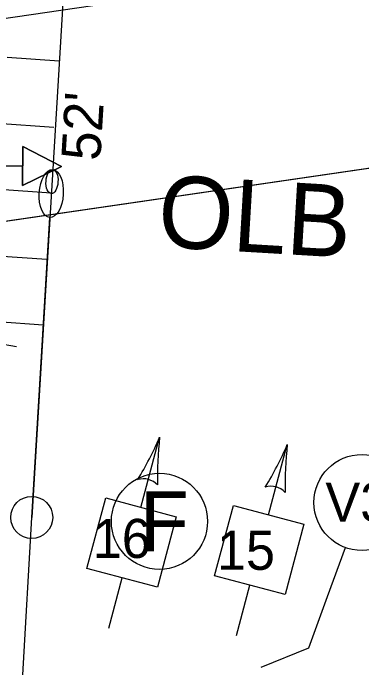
# Model space of a CAD drawing. Extents: x 647787 to 668496, y 640478 to 654412.
# Drawn here: x 661890.8 to 661919.8, y 647241.2 to 647296.2 of the extents above; entities that cross this region are included whole.
import ezdxf

# ---------------------------------------------------------------- set-up
doc = ezdxf.new("R2010")
doc.units = 0
for name, color, linetype in [('Default', 7, 'Continuous'), ('TEMP_SIGNAL_HEAD_STAGE 2', 7, 'Continuous'), ('TEMP_SIGNAL_HEAD_Stage 3', 7, 'Continuous'), ('TEMP_SIGNAL_HEAD_STAGE 4 SHILO', 7, 'Continuous'), ('TEMP_SIGNAL_HEAD_STAGE4', 7, 'Continuous'), ('TEMP_SIGNAL_POLES_STAGE 1A', 7, 'Continuous'), ('TEMP_SIGNAL_POLES_STAGE 5', 7, 'Continuous'), ('TEXT_TEMP_SIGNAL_POLES_STAGE 2', 7, 'Continuous'), ('TEXT_TEMP_SIGNAL_POLES_STAGE 5', 7, 'Continuous')]:
    doc.layers.add(name, color=color, linetype=linetype)

msp = doc.modelspace()

# ---------------------------------------------------------------- linework, layer by layer
at = {"layer": 'Default'}
for points in [[(662136.439, 647331.769), (661882.019, 647294.613), (661114.402, 647320.889)], [(662108.288, 647310.771), (661853.868, 647273.614), (661086.251, 647299.89)], [(662108.288, 647310.771), (661888.554, 647278.68)], [(662108.288, 647310.771), (661888.554, 647278.68)]]:
    msp.add_lwpolyline(points, dxfattribs=at)
at = {"layer": 'TEMP_SIGNAL_HEAD_STAGE 2'}
for p, q in [((661901.432, 647255.118), (661902.988, 647260.955)), ((661912.052, 647254.503), (661913.608, 647260.339)), ((661916.966, 647247.7), (661918.451, 647251.767)), ((661898.749, 647245.06), (661899.869, 647249.26)), ((661909.369, 647244.444), (661910.489, 647248.645)), ((661915.407, 647243.43), (661916.966, 647247.7)), ((661911.445, 647241.82), (661915.407, 647243.43))]:
    msp.add_line(p, q, dxfattribs=at)
for points in [[(661902.799, 647248.479), (661896.94, 647250.041), (661898.502, 647255.9), (661904.362, 647254.337)], [(661913.419, 647247.863), (661907.56, 647249.426), (661909.122, 647255.284), (661914.982, 647253.722)]]:
    msp.add_lwpolyline(points, close=True, dxfattribs=at)
msp.add_circle((661919.824, 647255.525), 4, dxfattribs=at)
for centre, radius, start, end in [((661875.97, 647272.726), 29.472, 328.7206, 336.4587), ((661932.282, 647257.708), 29.472, 173.6753, 181.4134), ((661886.59, 647272.111), 29.472, 328.7206, 336.4587), ((661942.902, 647257.093), 29.472, 173.6753, 181.4134), ((661901.632, 647255.866), 1.629, 43.2197, 106.9143), ((661912.252, 647255.25), 1.629, 43.2197, 106.9143)]:
    msp.add_arc(centre, radius, start, end, dxfattribs=at)
at = {"layer": 'TEMP_SIGNAL_HEAD_Stage 3'}
msp.add_line((661891.067, 647268.477), (661876.801, 647271.004), dxfattribs=at)
at = {"layer": 'TEMP_SIGNAL_HEAD_STAGE 4 SHILO'}
for points in [[(661891.574, 647281.911), (661891.611, 647285.148), (661894.818, 647283.492), (661891.574, 647281.911)], [(661891.574, 647281.911), (661891.611, 647285.148), (661894.818, 647283.492), (661891.574, 647281.911)], [(661889.993, 647283.548), (661891.593, 647283.53)], [(661889.993, 647283.548), (661891.593, 647283.53)]]:
    msp.add_lwpolyline(points, dxfattribs=at)
msp.add_lwpolyline([(661894.818, 647283.492), (661891.611, 647285.148), (661891.574, 647281.911)], close=True, dxfattribs=at)
msp.add_lwpolyline([(661894.818, 647283.492), (661891.611, 647285.148), (661891.574, 647281.911)], close=True, dxfattribs=at)
at = {"layer": 'TEMP_SIGNAL_HEAD_STAGE4'}
msp.add_line((661891.067, 647268.477), (661876.801, 647271.004), dxfattribs=at)
at = {"layer": 'TEMP_SIGNAL_POLES_STAGE 1A'}
for p, q in [((661895.478, 647306.186), (661892.345, 647254.281)), ((661894.637, 647292.251), (661890.3, 647292.547)), ((661883.789, 647287.48), (661894.174, 647286.77)), ((661893.974, 647281.271), (661889.637, 647281.567)), ((661892.345, 647254.281), (661893.851, 647279.236)), ((661883.213, 647276.494), (661893.599, 647275.784)), ((661893.311, 647270.29), (661888.974, 647270.587))]:
    msp.add_line(p, q, dxfattribs=at)
msp.add_circle((661892.345, 647254.281), 1.75, dxfattribs=at)
for centre, major_axis in [((661893.972, 647281.232), (0.121, 1.996)), ((661894.032, 647282.23), (-0.06, -0.998))]:
    msp.add_ellipse(centre, major_axis=major_axis, ratio=0.5, dxfattribs=at)
at = {"layer": 'TEMP_SIGNAL_POLES_STAGE 5'}
for p, q in [((661895.478, 647306.186), (661892.345, 647254.281)), ((661892.345, 647254.281), (661893.851, 647279.236)), ((661891.611, 647241.188), (661892.345, 647254.281))]:
    msp.add_line(p, q, dxfattribs=at)
msp.add_circle((661892.345, 647254.281), 1.75, dxfattribs=at)
for centre, major_axis in [((661893.972, 647281.232), (0.121, 1.996)), ((661894.032, 647282.23), (-0.06, -0.998))]:
    msp.add_ellipse(centre, major_axis=major_axis, ratio=0.5, dxfattribs=at)
at = {"layer": 'TEXT_TEMP_SIGNAL_POLES_STAGE 5'}
msp.add_circle((661902.975, 647253.953), 4, dxfattribs=at)

# ---------------------------------------------------------------- texts
at = {"layer": 'Default'}
msp.add_text('OLB', height=6, rotation=356.6181, dxfattribs=at).set_placement((661902.73, 647276.821))
msp.add_text('OLB', height=6, rotation=356.6181, dxfattribs=at).set_placement((661902.73, 647276.821))
at = {"layer": 'TEXT_TEMP_SIGNAL_POLES_STAGE 2'}
for s, p in [('V3', (661916.777, 647253.928)), ('16', (661897.42, 647250.908)), ('15', (661907.751, 647249.921))]:
    msp.add_text(s, height=3.25, dxfattribs=at).set_placement(p)
at = {"layer": 'TEXT_TEMP_SIGNAL_POLES_STAGE 5'}
msp.add_text("52'", height=3.25, rotation=86.5452, dxfattribs=at).set_placement((661898.042, 647283.915))
msp.add_text('F', height=5, dxfattribs=at).set_placement((661901.341, 647251.453))

doc.saveas('drawing.dxf')
